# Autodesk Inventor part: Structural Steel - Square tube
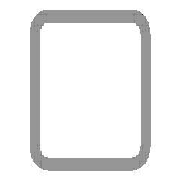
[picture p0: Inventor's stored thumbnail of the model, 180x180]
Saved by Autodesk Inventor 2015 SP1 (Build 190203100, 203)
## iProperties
_CCFamilyMember: 2
_CCFamilyDisplayName: ISO 4019 (Square) - Structural steels - Cold-formed, welded, structural hollow sections
_FrameMemberDoc: Frame Member File
_Version: 15.0.0
_GetPNFromCC: 1
Created: 2011-06
Part Number: Structural Steel - Square tube
Material: Stainless Steel
Document SubType Name: Modeling
Standard: ISO
Designer: Guilherme Augusto Franco de Souza
Standard Revision: Second edition 2001-09-01
Standards Organization: ISO
Language: en-US
Size Designation: 25x25x2
Categories: <MemberInstance><Categories><Category DisplayName="Structural Shapes" InternalName="089c4875-fa83-4c05-b084-43b9cc11f5ed" Mnemonic="GRDR"><CategoryParameter Dis
Stock Number: 25x25x2
Density: 8.08 g/cm^3
Description: ISO 4019 - 25x25x2
Appearance: Steel
G_L: 225,000 mm
G_W: 25,000 mm
G_H: 25,000 mm
+3FA14DB6-D65F-4EF1-82D6-2F48BBAF4B2E+CUTDETAIL1: Miter 45,00 deg
+8B08AE22-E64A-4B24-8CB4-2A9D26660AA5+CUTDETAIL2: Cut
IsCustomPart: 1
Author: Guilherme Augusto Franco de Souza
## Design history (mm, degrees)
node "Start plane"
node "End plane"
sketch "Sketch"
  geometry: L1 (-12.5, -8.5)-(-12.5, 8.5); L2 (-8.5, 12.5)-(8.5, 12.5); L3 (12.5, 8.5)-(12.5, -8.5); L4 (8.5, -12.5)-(-8.5, -12.5); L5 (-8.5, 10.5)-(8.5, 10.5); L6 (10.5, 8.5)-(10.5, -8.5); L7 (8.5, -10.5)-(-8.5, -10.5); L8 (-10.5, -8.5)-(-10.5, 8.5); L9 (0, 18.66)-(0, -18.66) reference; L10 (-18.66, 0)-(18.66, 0) reference; A1 r 4 centre (-8.5, -8.5) between (-12.5, -8.5) and (-8.5, -12.5); A2 r 4 centre (8.5, 8.5) between (12.5, 8.5) and (8.5, 12.5); A3 r 4 centre (-8.5, 8.5) between (-8.5, 12.5) and (-12.5, 8.5); A4 r 4 centre (8.5, -8.5) between (8.5, -12.5) and (12.5, -8.5); A5 r 2 centre (-8.5, 8.5) between (-8.5, 10.5) and (-10.5, 8.5); A6 r 2 centre (8.5, 8.5) between (10.5, 8.5) and (8.5, 10.5); A7 r 2 centre (8.5, -8.5) between (8.5, -10.5) and (10.5, -8.5); A8 r 2 centre (-8.5, -8.5) between (-10.5, -8.5) and (-8.5, -10.5)
  constraints: 16 end point, 16 point on circle, 8 centre point, 8 tangent, 4 parallel, 3 equal radius, 2 perpendicular, 7 other
  dimensions: "d7" = 4 radius of A1 (= G_IR); "d9" = 25 distance between parallel lines of L1 L3 (= G_W); "d11" = 25 distance between parallel lines of L2 L4 (= G_H); "d12" = 2 distance between parallel lines of L3 L6 (= G_T); "d15" = 12.5 distance between parallel lines of L9 L3 (= 0.5 x d9); "d16" = 12.5 distance between parallel lines of L2 L10 (= 0.5 x d11)
extrude "Body" new body sketch "Sketch" stored distance "d3" = 225 (= G_L); taper "d4" = 0 deg
node "Driven Length"
  sketch "Sketch3"
    geometry: L1 (0, 0)-(10, 0) reference
    constraints: 2 end point, 1 horizontal
  workplane "Work Plane3"
  sketch "Sketch4"
    geometry: L1 (-2, 25)-(12, 25) reference; L2 (-2, 224.859)-(12, 224.859) reference
    dimensions: "d18" = 199.85858 distance between parallel lines of L1 L2 (derived)
workplane "Work Plane4"
split "Split1"
workplane "Work Plane5"
split "Split2"
node "Hole2"
node "Hole4"
body "Solid1"
sketch "Sketch5"
  geometry: 4 further points
hole "Hole1" sketch "Sketch5" diameter "d19" = 6.6; stored, may be unused: countersink angle "d23" = 90 deg, drill point angle "d25" = 0 deg; dims "d20" = 6, "d21" = 4, "d22" = 2, "d24" = 8
sketch "Sketch6"
  geometry: 4 further points
hole "Hole3" sketch "Sketch6" diameter "d26" = 6.6; stored, may be unused: countersink angle "d30" = 90 deg, drill point angle "d32" = 0 deg; dims "d27" = 6, "d28" = 4, "d29" = 2, "d31" = 8
other parameters: "G_W" = 25 [user parameter; used in 1 equation term], "G_H" = 25 [user parameter; used in 1 equation term], "G_T" = 2 [user parameter; used in 1 equation term], "G_IR" = 4 [user parameter; used in 1 equation term], "G_L" = 225 [user parameter; used in 1 equation term], "G_OFFSET_START" = -25 [user parameter; used in 1 equation term], "G_OFFSET_END" = -0.14142 [user parameter; used in 1 equation term], "d13" = 25 (= -G_OFFSET_START), "d14" = 224.85858 (= G_OFFSET_END + B_L), "B_L" = 225 [user parameter; used in 1 equation term], "d17" = 90 deg, "MAS" = 0.136 [user parameter]
